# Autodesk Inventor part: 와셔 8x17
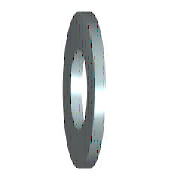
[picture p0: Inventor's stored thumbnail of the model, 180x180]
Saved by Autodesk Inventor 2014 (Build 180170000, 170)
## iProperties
Created: 2012-02
Part Number: 와셔 8x17
Material: 강철, 연강
Description: 평면 와셔
Document SubType Name: Modeling
Standard: KS B 1326
Designer: mduedu
Standards Organization: KS
Language: ko-KR
Size Designation: 8x17
Categories: <MemberInstance><Categories><Category DisplayName="조임쇠" InternalName="e4da775c-781d-43d5-af7c-5136215cf5a6" Mnemonic="FSTN"><Category DisplayName="와셔" InternalN
Density: 7.86 g/cm^3
Appearance: 파란색 - 벽 페인트 - 광택
Mass: 2.05445 g
Surface Area: 4.57416 cm^2
Volume: 0.261381 cm^3
IsCustomPart: 1
Author: mduedu
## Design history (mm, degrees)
sketch "스케치"
  geometry: C1 r 8.5 at (0, 0); C2 r 4.5 at (0, 0); 1 further point
  constraints: 2 centre point, 2 coincident
  dimensions: "d0" = 9 diameter of C2 (= SD1); "d1" = 17 diameter of C1 (= SD2)
extrude "본체" new body sketch "스케치" distance "d2" = 1.6 (= SD); taper "d3" = 0 deg
workaxis "Work Axis1"
workplane "Work Plane1"
body "Solid1"
other parameters: "SD1" = 9 [user parameter; used in 1 equation term], "SD2" = 17 [user parameter; used in 1 equation term], "SD" = 1.6 [user parameter; used in 1 equation term], "d4" = 0, "d5" = 0, "d6" = 0, "d7" = 0, "NND" = 8 [user parameter]
